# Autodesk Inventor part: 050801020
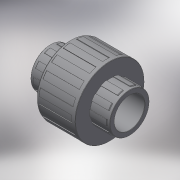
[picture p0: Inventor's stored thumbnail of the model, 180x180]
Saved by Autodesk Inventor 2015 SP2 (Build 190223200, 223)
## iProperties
Created: 2017-10
Part Number: 050801020
Material: Generic
Description: PLASSON THR.UNION+O RING PVC 2"
Document SubType Name: Modeling
Designer: KIM
Density: 1 g/cm^3
Appearance: Default
Author: KIM
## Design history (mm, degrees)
derived "050801.ipt"
feature "Solid1::050801.ipt"
tag "TaggingFeature1"
body "Solid1"
other parameters: "d0" = 92, "d3" = 56.656, "d4" = 56.656, "d5" = 75.91904, "d6" = 73.64147, "d7" = 75.91904, "d8" = 96, "d10" = 34, "d11" = 50.9904, "d14" = 25.5, "d17" = 3.4, "d19" = 94.08, "d20" = 3.4, "d21" = 1.44, "d25" = 9.6, "d26" = 4.8, "d27" = 33.84, "d28" = 0, "d32" = 9.6, "d33" = 4.8, "d35" = 0, "d39" = 0.16, "d45" = 1.13879, "d49" = 360 deg, "d51" = 0.96, "d55" = 360 deg, "d57" = 34, "d58" = 25.5, "d_" = 16, "E_" = 96, "H_" = 92, "l_" = 14, "lt_" = 34, "Z_" = 11, "G_" = 56.656, "d24" = 37.6, "d40" = 1.13879, "d44" = 0.96
